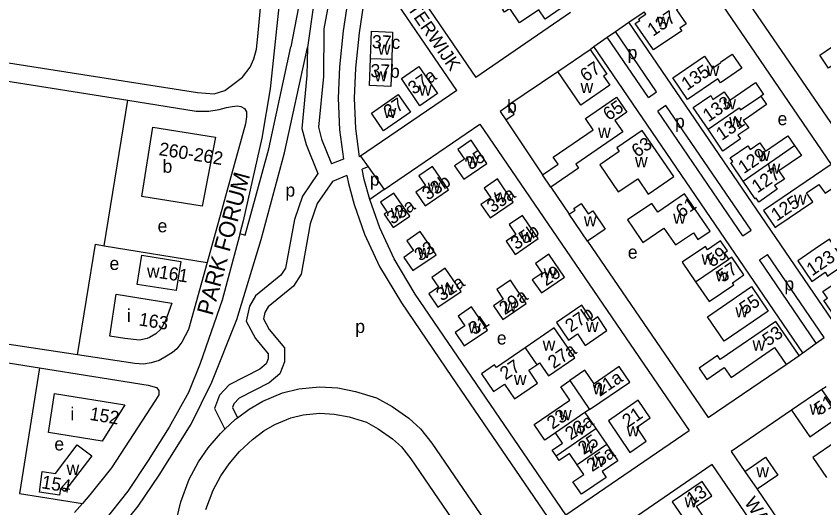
# Model space of a CAD drawing. Extents: x 154320 to 156262, y 382651 to 384180.
# Drawn here: x 155307.4 to 155553.7, y 383173 to 383322.8 of the extents above; entities that cross this region are included whole.
import ezdxf

# ---------------------------------------------------------------- set-up
doc = ezdxf.new("R2010")
doc.units = 0
for name, color, linetype in [('BLT_Basislijn', 7, 'Continuous'), ('BLT_Bebouwing', 7, 'Continuous'), ('BLT_Centroide', 7, 'Continuous'), ('BLT_Huisnummer', 7, 'Continuous'), ('BLT_Huisnummer_reeks', 7, 'Continuous'), ('BLT_Onderverdeling_panden', 7, 'Continuous'), ('BLT_Straatnaam', 7, 'Continuous')]:
    doc.layers.add(name, color=color, linetype=linetype)

msp = doc.modelspace()

# ---------------------------------------------------------------- linework, layer by layer
at = {"layer": 'BLT_Basislijn'}
for p, q in [((155521.89, 383339.79), (155585.65, 383246.5)), ((155516.11, 383335.84), (155555.91, 383277.62)), ((155476.44, 383323.87), (155447.55, 383304.12)), ((155494.24, 383320.89), (155498.93, 383324.09)), ((155490.11, 383318.07), (155494.24, 383320.89)), ((155557.81, 383227.88), (155494.24, 383320.89)), ((155487.63, 383316.38), (155490.11, 383318.07)), ((155502.68, 383299.69), (155490.11, 383318.07)), ((155217.4, 383316.76), (155341.44, 383297.14)), ((155483.51, 383313.56), (155487.63, 383316.38)), ((155500.2, 383298), (155487.63, 383316.38)), ((155482.38, 383312.57), (155483.51, 383313.56)), ((155547.28, 383220.24), (155483.51, 383313.56)), ((155441.77, 383300.17), (155412.12, 383279.91)), ((155500.2, 383298), (155502.68, 383299.69)), ((155334.27, 383252.87), (155341.44, 383297.14)), ((155505.52, 383295.52), (155503.05, 383293.82)), ((155531.47, 383257.56), (155505.52, 383295.52)), ((155528.99, 383255.87), (155503.05, 383293.82)), ((155419.65, 383270), (155448.82, 383289.85)), ((155448.82, 383289.85), (155512.59, 383196.56)), ((155412.42, 383280.11), (155414.7, 383276.89)), ((155414.7, 383276.89), (155412.9, 383276.16)), ((155414.7, 383276.89), (155419.65, 383270)), ((155470.4, 383270.68), (155476.02, 383262.48)), ((155419.65, 383270), (155415.2, 383266.98)), ((155528.99, 383255.87), (155531.47, 383257.56)), ((155334.27, 383252.87), (155365.61, 383247.79)), ((155481.65, 383254.26), (155518.37, 383200.51)), ((155534.02, 383248.51), (155536.48, 383250.22)), ((155551.33, 383223.18), (155534.02, 383248.51)), ((155553.76, 383224.94), (155536.48, 383250.22)), ((155551.33, 383223.18), (155553.76, 383224.94)), ((155547.28, 383220.24), (155551.33, 383223.18)), ((155546.13, 383219.41), (155547.28, 383220.24)), ((155518.37, 383200.51), (155542.22, 383216.71)), ((155440.17, 383213.02), (155470.8, 383168.2)), ((155554.33, 383209.93), (155553.09, 383209.08)), ((155543.82, 383202.76), (155525.42, 383190.19)), ((155475.03, 383170.88), (155512.59, 383196.56)), ((155525.42, 383190.19), (155529.61, 383184.14)), ((155519.64, 383186.24), (155482.08, 383160.56)), ((155533.34, 383178.68), (155570.55, 383124.16))]:
    msp.add_line(p, q, dxfattribs=at)
for points in [[(155386.23, 383419.48), (155386.58, 383417.36), (155389.18, 383382.39), (155389.65, 383369.28), (155389.42, 383356.16), (155387.53, 383325.56), (155384.81, 383300.64), (155382.33, 383285.63), (155376.66, 383260.47), (155375.61, 383256.54)], [(155420.78, 383399.29), (155411.93, 383386.75), (155410.24, 383382.5), (155409.08, 383372.12), (155406.49, 383365.71), (155405.77, 383362.27), (155405.72, 383354.87), (155404.9, 383338.55), (155401.26, 383318.86), (155401.08, 383304.41), (155399.6, 383288.97), (155400.55, 383285.26), (155403.6, 383277.76)], [(155427.92, 383392.74), (155427.38, 383392), (155420.75, 383378.59), (155417.28, 383369.55), (155415.24, 383362.63), (155413.37, 383355.63), (155410.73, 383342.59), (155407.13, 383318.3), (155405.98, 383307.32), (155405.59, 383297.75), (155406.01, 383288.13), (155407.17, 383279.22)], [(155412.12, 383279.91), (155410.99, 383288.56), (155410.59, 383297.76), (155410.96, 383306.96), (155412.09, 383317.67), (155415.66, 383341.72), (155418.24, 383354.49), (155420.06, 383361.28), (155422.02, 383367.95), (155425.33, 383376.59), (155431.66, 383389.39)], [(155402.53, 383369.27), (155401.34, 383351.06), (155400.02, 383339.82), (155396.19, 383313.18)], [(155397.11, 383356.92), (155396.22, 383344.6), (155393.98, 383328.27), (155391.12, 383313.39)], [(155441.77, 383300.17), (155418.3, 383334.5), (155424.08, 383338.45)], [(155424.08, 383338.45), (155447.55, 383304.12)], [(155221.43, 383321.6), (155362.65, 383299.48), (155367.81, 383299.16), (155371.04, 383300.13), (155373.46, 383301.91), (155376.37, 383304.17), (155378.79, 383307.23), (155379.92, 383309.82), (155380.73, 383312.72), (155381.05, 383316.6), (155382.68, 383334.05)], [(155320.24, 383140.84), (155319.93, 383143.05), (155320.31, 383144.91), (155321.59, 383147.08), (155335.71, 383162.43), (155344.62, 383173.54), (155351.02, 383183), (155360.81, 383198.54), (155367.06, 383211.27), (155374.73, 383230.39), (155382.06, 383254.72), (155389.26, 383281.18), (155396.19, 383313.18)], [(155375.61, 383256.54), (155377.26, 383256.1), (155384.4, 383282.37), (155391.12, 383313.39)], [(155396.19, 383313.18), (155396.08, 383304.68), (155394.54, 383288.58), (155395.79, 383283.69), (155399.4, 383274.8)], [(155457.45, 383295.44), (155457.31, 383295.65), (155472.58, 383305.88)], [(155341.44, 383297.14), (155362.33, 383293.83), (155366.2, 383293.83), (155369.27, 383294.32), (155371.53, 383294.96), (155373.3, 383295.29), (155374.92, 383295.45), (155375.88, 383295.29), (155377.01, 383294.64), (155377.66, 383293.67), (155377.66, 383292.06), (155377.34, 383289.96), (155365.61, 383247.79)], [(155456.72, 383291.17), (155467.86, 383274.42)], [(155407.17, 383279.22), (155403.6, 383277.76)], [(155415.2, 383266.98), (155413.55, 383273.01), (155412.9, 383276.16)], [(155399.4, 383274.8), (155394.69, 383267.99), (155392.23, 383260.79), (155389.54, 383246.07), (155388.15, 383243.89), (155380.41, 383237.56), (155378.52, 383234.44), (155377.49, 383229.85), (155380.35, 383224.55), (155384.23, 383219.91), (155384.24, 383218.4), (155383.65, 383216.88), (155381.75, 383215.3), (155372.32, 383210.49), (155369.44, 383207.36), (155367.88, 383203.31), (155371.03, 383196.94)], [(155408.19, 383274.23), (155403.86, 383272.46), (155399.2, 383265.72), (155397.08, 383259.52), (155394.28, 383244.21), (155391.94, 383240.53), (155384.24, 383234.23), (155383.22, 383232.55), (155382.78, 383230.58), (155384.52, 383227.36), (155389.21, 383221.74), (155389.25, 383217.49), (155387.84, 383213.86), (155384.52, 383211.1), (155375.39, 383206.44), (155373.76, 383204.67), (155373.33, 383203.56), (155374.87, 383200.46)], [(155408.19, 383274.23), (155408.69, 383271.84), (155410.45, 383265.39), (155413.63, 383256.42), (155418.19, 383246.56), (155424.86, 383235.42), (155440.17, 383213.02)], [(155475.03, 383170.88), (155429.07, 383238.12), (155422.61, 383248.9), (155418.27, 383258.31), (155415.23, 383266.89), (155415.2, 383266.98)], [(155375.61, 383256.54), (155375.38, 383255.54), (155370.17, 383236.25), (155363.55, 383217), (155360, 383208.17)], [(155326.09, 383219.62), (155331.56, 383253.28), (155334.27, 383252.87)], [(155365.61, 383247.79), (155359.91, 383227.31), (155357.97, 383223.44), (155356.36, 383221.5), (155355.06, 383220.37), (155353.29, 383219.24), (155351.03, 383217.95), (155348.61, 383217.14), (155346.19, 383216.82), (155343.61, 383216.98), (155326.09, 383219.62)], [(155224.98, 383169.03), (155219.5, 383178.23), (155214.33, 383188.89), (155209.49, 383201.32), (155201.74, 383226.51), (155201.58, 383230.38), (155202.23, 383232.64), (155203.19, 383233.45), (155204.32, 383233.93), (155205.94, 383233.61), (155208.36, 383232.64), (155314.48, 383215.66)], [(155326.09, 383219.62), (155289.06, 383225.21)], [(155314.48, 383215.66), (155308.4, 383177.4), (155327.61, 383174.35)], [(155314.48, 383215.66), (155347.64, 383210.36), (155350.22, 383209.71), (155350.87, 383208.75), (155350.87, 383207.45), (155349.9, 383205.84), (155336.5, 383185.17), (155329.89, 383176.94), (155327.61, 383174.35)], [(155374.87, 383200.46), (155378.49, 383203.13), (155382.64, 383205.55), (155388.58, 383208.07), (155393.6, 383209.3), (155399.9, 383209.93), (155405.44, 383209.53), (155410.91, 383208.49), (155417.32, 383206.53), (155422.05, 383203.92), (155427.12, 383200.3), (155430.7, 383197.1), (155434.16, 383192.75), (155454.38, 383163.17)], [(155360, 383208.17), (155354.11, 383197.62), (155347.61, 383187.46), (155341.47, 383178.13), (155334.03, 383168.79)], [(155365.25, 383172.56), (155367.45, 383178.44), (155369.85, 383182.81), (155372.33, 383186.43), (155375.5, 383190.15), (155379.44, 383193.89), (155382.9, 383196.44), (155386.23, 383198.38), (155391.11, 383200.46), (155394.96, 383201.39), (155400.02, 383201.9), (155404.4, 383201.59), (155408.99, 383200.71), (155414.18, 383199.12), (155417.78, 383197.14), (155422.11, 383194.05), (155424.86, 383191.59), (155427.72, 383187.99), (155481.67, 383109.07)], [(155371.03, 383196.94), (155374.29, 383200.03), (155374.87, 383200.46)], [(155366.16, 383128.03), (155363.28, 383131.87), (155360.36, 383137.25), (155358.21, 383142.41), (155357.78, 383143.7), (155356.16, 383150.24), (155355.43, 383155.5), (155355.22, 383162.17), (155355.91, 383167.61), (155357.57, 383174.87), (155360.16, 383181.79), (155363.03, 383187), (155365.96, 383191.29), (155369.69, 383195.66), (155371.03, 383196.94)], [(155564.78, 383120.21), (155519.64, 383186.24)], [(155327.61, 383174.35), (155325.21, 383171.61)]]:
    msp.add_lwpolyline(points, dxfattribs=at)
at = {"layer": 'BLT_Bebouwing'}
for p, q in [((155472.58, 383305.88), (155482.38, 383312.57)), ((155470.4, 383270.68), (155467.86, 383274.42)), ((155481.65, 383254.26), (155476.02, 383262.48)), ((155518.16, 383231.21), (155531.56, 383240.43)), ((155531.56, 383240.43), (155536.68, 383232.97)), ((155523.29, 383223.76), (155518.16, 383231.21)), ((155536.68, 383232.97), (155523.29, 383223.76)), ((155542.22, 383216.71), (155546.13, 383219.41)), ((155553.09, 383209.08), (155543.82, 383202.76)), ((155482.22, 383202.97), (155480.83, 383202.03)), ((155480.83, 383202.03), (155484.17, 383197.15)), ((155484.17, 383197.15), (155487.5, 383192.27)), ((155529.61, 383184.14), (155533.34, 383178.68))]:
    msp.add_line(p, q, dxfattribs=at)
for points in [[(155468.15, 383333.34), (155473.62, 383325.15), (155468.72, 383321.82), (155466.76, 383324.72), (155460.85, 383320.69), (155457.88, 383325.09), (155456.31, 383324.03), (155455.74, 383324.88), (155468.15, 383333.34)], [(155511.44, 383332.68), (155511.76, 383332.22), (155511.28, 383331.89), (155513.9, 383328.28), (155508.71, 383324.68), (155511.7, 383320.41), (155509.79, 383319.11), (155510.34, 383318.33), (155501.73, 383312.47), (155496.17, 383320.48), (155497.58, 383321.43), (155497.23, 383321.93), (155498.53, 383322.83), (155499.39, 383323.42), (155498.93, 383324.09)], [(155415.41, 383309.88), (155415.71, 383318.16), (155422.2, 383317.93), (155421.9, 383309.65)], [(155482.38, 383312.57), (155487.45, 383305.14), (155486.53, 383304.52), (155488.41, 383301.76), (155479.54, 383295.69), (155472.58, 383305.88)], [(155421.9, 383309.65), (155421.61, 383301.38), (155415.12, 383301.6), (155415.41, 383309.88)], [(155518.43, 383288.36), (155513.83, 383294.9), (155519.22, 383298.57), (155519.85, 383297.39), (155523.29, 383299.68), (155525, 383297.17), (155532.81, 383302.55), (155535.29, 383298.95), (155534.45, 383298.38)], [(155467.86, 383274.42), (155472.67, 383277.7), (155471.18, 383279.85), (155483.31, 383288.15), (155480.95, 383291.6), (155490.46, 383298.09), (155493.62, 383293.48), (155489.97, 383290.99), (155492.36, 383287.5), (155478.07, 383277.74), (155478.91, 383276.5), (155470.4, 383270.68)], [(155534.45, 383298.38), (155536.18, 383295.82), (155530.04, 383291.61), (155529.11, 383290.97), (155530.77, 383288.72), (155527.49, 383286.48), (155528.24, 383285.36), (155522.82, 383281.69), (155518.43, 383288.36)], [(155457.45, 383295.44), (155454.98, 383293.69), (155456.72, 383291.17)], [(155456.72, 383291.17), (155459.2, 383292.9), (155457.45, 383295.44)], [(155529.05, 383272.55), (155525.28, 383278.1), (155525.89, 383278.51), (155525.12, 383279.64), (155530.44, 383283.24), (155531.2, 383282.11), (155534.16, 383284.15), (155535.87, 383281.68), (155542.69, 383286.34), (155544.76, 383283.33)], [(155544.76, 383283.33), (155546.82, 383280.32), (155539.98, 383275.62), (155541.67, 383273.17), (155538.67, 383271.16), (155539.44, 383270.04), (155533.8, 383266.17), (155533.01, 383267.32), (155532.74, 383267.14), (155529.05, 383272.55)], [(155555.91, 383277.62), (155535.85, 383263.95), (155535.27, 383263.55), (155538.79, 383258.4), (155539.37, 383258.8), (155550.28, 383266.23), (155548.41, 383268.96), (155552.18, 383271.54), (155554.05, 383268.82), (155559.41, 383272.49)], [(155476.02, 383262.48), (155477.82, 383263.72), (155477.48, 383264.22), (155479.64, 383265.69), (155481.81, 383262.52), (155483.21, 383263.48), (155487.02, 383257.92), (155481.65, 383254.26)], [(155568.86, 383258.73), (155557.86, 383251.18), (155555.35, 383254.85), (155551.05, 383251.9), (155545.74, 383248.23), (155550.01, 383242), (155554.04, 383244.77), (155554.82, 383243.61), (155555.61, 383244.15), (155566.05, 383251.29), (155566.91, 383250.06), (155572.26, 383253.75)], [(155524.7, 383248.77), (155523.37, 383250.71), (155524.25, 383251.32), (155522.19, 383254.33), (155518.23, 383251.63), (155517.54, 383252.64), (155510.49, 383247.82), (155514.57, 383241.84)], [(155514.57, 383241.84), (155518.66, 383235.85), (155526.18, 383240.97), (155525.78, 383241.55), (155529.29, 383243.95), (155525.58, 383249.37), (155524.7, 383248.77)], [(155558.84, 383228.62), (155553.67, 383236.14), (155554.73, 383236.89), (155553.37, 383238.87), (155559.31, 383242.99), (155560.68, 383241), (155564.39, 383243.55), (155564.69, 383243.12), (155564.47, 383242.97), (155567.12, 383239.1), (155564.54, 383237.32), (155566.61, 383234.3)], [(155546.13, 383219.41), (155539.02, 383229.79), (155522.1, 383218.19), (155521.26, 383219.4), (155515.66, 383215.54), (155518.01, 383212.12), (155523.26, 383215.73), (155525.36, 383212.74), (155538.67, 383221.86), (155542.22, 383216.71)], [(155466.12, 383216.61), (155466.97, 383217.18), (155469.67, 383213.24), (155477.7, 383218.72), (155471.48, 383227.83), (155462.6, 383221.76)], [(155462.6, 383221.76), (155453.84, 383215.78), (155453.28, 383216.6), (155449.27, 383213.87), (155452.94, 383208.47), (155456.25, 383210.73), (155459.35, 383206.19), (155466.4, 383211.02), (155463.7, 383214.96), (155466.12, 383216.61)], [(155482.22, 383202.97), (155494.54, 383211.3), (155491.26, 383216.05), (155483.6, 383210.82), (155480.78, 383214.94), (155476.21, 383211.82)], [(155471.85, 383195.86), (155468.55, 383193.62), (155465.34, 383198.36), (155476.24, 383205.79), (155473.43, 383209.92), (155473.43, 383209.92), (155476.21, 383211.82)], [(155543.82, 383202.76), (155549.35, 383194.7), (155558.6, 383201), (155553.09, 383209.08)], [(155472.02, 383188.85), (155470.82, 383190.61), (155473.96, 383192.76), (155471.85, 383195.86)], [(155565.97, 383190.26), (155562.65, 383195.11), (155557.9, 383191.86), (155557.08, 383193.05), (155550.27, 383188.4), (155554.5, 383182.23)], [(155487.5, 383192.27), (155490.84, 383187.39), (155486.07, 383184.13), (155487.31, 383182.31), (155479.77, 383177.15), (155477.18, 383180.95), (155480.5, 383183.2), (155478.5, 383186.12)], [(155478.5, 383186.12), (155476.15, 383189.57), (155473, 383187.42), (155472.02, 383188.85)], [(155529.61, 383184.14), (155535.9, 383188.46), (155539.65, 383182.98), (155533.34, 383178.68)]]:
    msp.add_lwpolyline(points, dxfattribs=at)
for points in [[(155552.46, 383310.85), (155568.52, 383321.84), (155568.52, 383321.84), (155568.83, 383321.38), (155573.89, 383324.84), (155577.93, 383318.97), (155568.15, 383312.27), (155566.45, 383314.72), (155555.11, 383306.97)], [(155507.58, 383303.99), (155517.24, 383310.58), (155519.75, 383306.9), (155522.28, 383308.66), (155522.2, 383308.78), (155525.71, 383311.22), (155528.65, 383306.9), (155522.16, 383302.45), (155521.3, 383303.68), (155512.11, 383297.39)], [(155424.86, 383303.73), (155430.22, 383307.41), (155435.86, 383299.18), (155430.51, 383295.45)], [(155423.93, 383298.89), (155427.62, 383293.48), (155419.37, 383287.85), (155415.7, 383293.22)], [(155345.72, 383267.84), (155349.1, 383288.99), (155368.19, 383285.95), (155364.09, 383264.89)], [(155498.3, 383287.92), (155490.52, 383282.62), (155491.29, 383281.5), (155485.35, 383277.46), (155490.96, 383269.23), (155496.91, 383273.27), (155496.91, 383273.27), (155500.1, 383268.59), (155507.89, 383273.9), (155507.89, 383273.9)], [(155446.11, 383284.96), (155444.53, 383283.88), (155442.04, 383282.19), (155444.06, 383279.21), (155441.09, 383277.19), (155443.89, 383273.12), (155450.93, 383277.94)], [(155434.37, 383276.98), (155430.22, 383274.15), (155432.26, 383271.19), (155429.28, 383269.17), (155432.11, 383265.02), (155439.21, 383269.88)], [(155458.92, 383266.17), (155454.13, 383273.21), (155450.07, 383270.41), (155452.09, 383267.45), (155449.12, 383265.42), (155451.9, 383261.34)], [(155422.58, 383268.87), (155418.52, 383266.1), (155420.54, 383263.08), (155419.57, 383262.42), (155422.34, 383258.38), (155427.4, 383261.81)], [(155511.21, 383268.64), (155503.06, 383263.07), (155501.23, 383265.74), (155493.82, 383260.7), (155495.32, 383258.5), (155498.48, 383253.88), (155504.89, 383258.25), (155508.43, 383253.1), (155513.88, 383256.82), (155515.29, 383254.75), (155518.97, 383257.29)], [(155461.75, 383262.05), (155457.7, 383259.29), (155459.75, 383256.3), (155456.77, 383254.27), (155459.55, 383250.19), (155466.57, 383255.01)], [(155428.39, 383245.27), (155435.43, 383250.08), (155430.61, 383257.14), (155426.56, 383254.33), (155428.6, 383251.38), (155425.62, 383249.31)], [(155345.73, 383249.98), (155357.58, 383248.09), (155356.17, 383239.21), (155344.32, 383241.09)], [(155469.81, 383250.28), (155465.72, 383247.49), (155467.74, 383244.52), (155464.78, 383242.51), (155467.56, 383238.46), (155474.6, 383243.27)], [(155436.2, 383240.2), (155433.24, 383238.16), (155436.02, 383234.12), (155443.05, 383238.92), (155438.24, 383245.97), (155434.16, 383243.2)], [(155458.08, 383242.32), (155453.92, 383239.49), (155455.92, 383236.53), (155452.95, 383234.51), (155455.79, 383230.35), (155462.91, 383235.22)], [(155337.94, 383238.06), (155354.88, 383235.35), (155352.93, 383229.97), (155351.52, 383227.49), (155350.03, 383226.05), (155348.03, 383224.9), (155347.4, 383224.58), (155345.06, 383224.11), (155340.5, 383224.57), (155335.92, 383225.33)], [(155446.28, 383234.21), (155442.22, 383231.43), (155444.25, 383228.45), (155441.27, 383226.44), (155444.04, 383222.38), (155451.08, 383227.18)], [(155479.84, 383234.73), (155472.15, 383229.49), (155475.82, 383224.12), (155478.54, 383225.99), (155480.92, 383222.51), (155487.53, 383227.03), (155484.71, 383231.15), (155483.06, 383230.02)], [(155319.07, 383207.84), (155340.56, 383204.4), (155333.65, 383193.37), (155317.26, 383195.96)], [(155500.76, 383200.4), (155497.09, 383205.77), (155487.98, 383199.53), (155494.54, 383189.93), (155499.52, 383193.31), (155496.64, 383197.59)], [(155315.37, 383184.06), (155319.4, 383183.45), (155326.06, 383192.22), (155330.46, 383188.89), (155322.17, 383177.96), (155320.91, 383178.9), (155320.61, 383176.9), (155314.48, 383177.79)], [(155516.52, 383181.09), (155507.42, 383174.85), (155514.21, 383164.97), (155518.61, 383167.96), (155514.81, 383173.49), (155519.52, 383176.69)]]:
    msp.add_lwpolyline(points, close=True, dxfattribs=at)
at = {"layer": 'BLT_Onderverdeling_panden'}
for p, q in [((155415.41, 383309.88), (155421.9, 383309.65)), ((155529.05, 383272.55), (155544.76, 383283.33)), ((155514.57, 383241.84), (155524.7, 383248.77)), ((155462.6, 383221.76), (155466.12, 383216.61)), ((155476.21, 383211.82), (155482.22, 383202.97)), ((155480.83, 383202.03), (155471.85, 383195.86)), ((155472.02, 383188.85), (155484.17, 383197.15)), ((155487.5, 383192.27), (155478.5, 383186.12))]:
    msp.add_line(p, q, dxfattribs=at)
msp.add_lwpolyline([(155518.43, 383288.36), (155527.85, 383294.81), (155528.25, 383294.22), (155534.45, 383298.38)], dxfattribs=at)

# ---------------------------------------------------------------- texts
at = {"layer": 'BLT_Centroide'}
for s, p in [('w', (155502.75, 383319.55)), ('w', (155417.7, 383311.02)), ('p', (155493.83, 383309.69)), ('w', (155517.94, 383304.57)), ('w', (155416.66, 383302.87)), ('w', (155479.49, 383299.32)), ('w', (155430.2, 383298.59)), ('b', (155457.09, 383293.3)), ('w', (155523.02, 383294.38)), ('w', (155419.46, 383291.76)), ('e', (155539.55, 383289.56)), ('p', (155508.29, 383288.72)), ('w', (155524.81, 383288.96)), ('w', (155484.84, 383285.69)), ('w', (155444.66, 383276.96)), ('w', (155533.42, 383278.68)), ('b', (155352.04, 383275.07)), ('w', (155496.08, 383276.76)), ('w', (155536.53, 383274.8)), ('p', (155415.24, 383271.15)), ('p', (155389.51, 383267.81)), ('w', (155432.88, 383268.99)), ('w', (155453.07, 383266.07)), ('w', (155544.54, 383265.37)), ('w', (155421.66, 383261.24)), ('w', (155480.5, 383258.75)), ('w', (155507.73, 383259.53)), ('e', (155350.53, 383256.93)), ('w', (155461.26, 383253.94)), ('w', (155429.85, 383249.11)), ('e', (155493.9, 383248.91)), ('e', (155335.88, 383245.47)), ('w', (155516.37, 383247.13)), ('w', (155347.29, 383243.15)), ('w', (155468.24, 383242.92)), ('w', (155520.65, 383242.02)), ('w', (155436.92, 383237.89)), ('p', (155541.63, 383239.23)), ('w', (155456.13, 383232.78)), ('i', (155341.17, 383229.59)), ('w', (155526.7, 383231.05)), ('p', (155410.81, 383226.28)), ('w', (155445.23, 383226.17)), ('w', (155481.1, 383226.53)), ('e', (155453.96, 383222.77)), ('w', (155467.94, 383220.9)), ('w', (155531.92, 383220.92)), ('w', (155459.16, 383210.42)), ('w', (155483.22, 383207.58)), ('i', (155323.96, 383199.64)), ('w', (155549.32, 383201.43)), ('w', (155472.89, 383199.72)), ('w', (155477.09, 383195.3)), ('w', (155493.55, 383194.76)), ('e', (155319.06, 383190.5)), ('w', (155479.89, 383189.6)), ('w', (155483.01, 383185.5)), ('w', (155322.78, 383183.06)), ('w', (155533.08, 383182.31)), ('w', (155511.2, 383173.17))]:
    msp.add_text(s, height=4, dxfattribs=at).set_placement(p)
at = {"layer": 'BLT_Huisnummer'}
for s, rotation, p in [('137', 34.3538, (155501.58, 383316.46)), ('37c', 358.3536, (155415.86, 383313.02)), ('37b', 358.3536, (155415.38, 383304.2)), ('67', 34.3538, (155481.08, 383302.6)), ('135', 34.3538, (155511.95, 383299.98)), ('37a', 34.3536, (155428.6, 383298.73)), ('37', 34.3536, (155421.17, 383291.57)), ('65', 34.3538, (155488.08, 383290.8)), ('133', 34.3538, (155518.48, 383290.4)), ('131', 34.3538, (155522.52, 383284.74)), ('63', 34.3538, (155496.76, 383279.59)), ('129', 34.3538, (155529.27, 383274.62)), ('35', 34.3538, (155445.94, 383275.72)), ('127', 34.3538, (155533.4, 383268.74)), ('33b', 34.3538, (155432.91, 383266.52)), ('35a', 34.3538, (155452.63, 383262.71)), ('125', 34.3538, (155539.29, 383260.14)), ('33a', 34.3538, (155422.08, 383259.17)), ('61', 34.3538, (155510.26, 383261.19)), ('35b', 34.3538, (155459.91, 383251.46)), ('33', 34.3538, (155430.56, 383247.96)), ('59', 34.3538, (155519.61, 383246.17)), ('123', 34.3538, (155550.09, 383243.49)), ('57', 34.3538, (155522.86, 383241.5)), ('161', 350.9731, (155350.75, 383243.01)), ('29', 34.3538, (155468.98, 383240.44)), ('31a', 34.3538, (155437.19, 383235.81)), ('29a', 34.3538, (155456.41, 383231.65)), ('55', 34.3538, (155529.65, 383231.69)), ('27b', 34.3538, (155476.51, 383226.31)), ('163', 350.9731, (155344.65, 383228.61)), ('31', 34.3538, (155447.12, 383225.5)), ('53', 34.3538, (155536.66, 383222.08)), ('27a', 34.3538, (155471.26, 383215.21)), ('27', 34.3538, (155456.61, 383211.8)), ('21a', 34.3538, (155485.35, 383206.77)), ('51', 34.3538, (155552.42, 383201.02)), ('152', 350.534, (155329.64, 383199.85)), ('23', 34.3538, (155470.93, 383196.76)), ('21', 34.3538, (155493.9, 383197.36)), ('23a', 34.3538, (155476.5, 383193.48)), ('25', 34.3538, (155480.44, 383189.05)), ('25a', 34.3538, (155483.02, 383183.85)), ('154', 350.534, (155314.94, 383179.03)), ('13', 34.3538, (155513.48, 383173.64))]:
    msp.add_text(s, height=4, rotation=rotation, dxfattribs=at).set_placement(p)
at = {"layer": 'BLT_Huisnummer_reeks'}
msp.add_text('260-262', height=4, rotation=350.9731, dxfattribs=at).set_placement((155350.75, 383280.48))
at = {"layer": 'BLT_Straatnaam'}
for s, height, rotation, p in [('WATERWIJK', 4, 304.5737, (155421.69, 383332.19)), ('PARK FORUM', 5, 74.9874, (155367.26, 383231.36)), ('WATERWIJK', 4, 304.5737, (155529.27, 383174.65))]:
    msp.add_text(s, height=height, rotation=rotation, dxfattribs=at).set_placement(p)

doc.saveas('drawing.dxf')
